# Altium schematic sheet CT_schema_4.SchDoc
size 578 x 363 mm
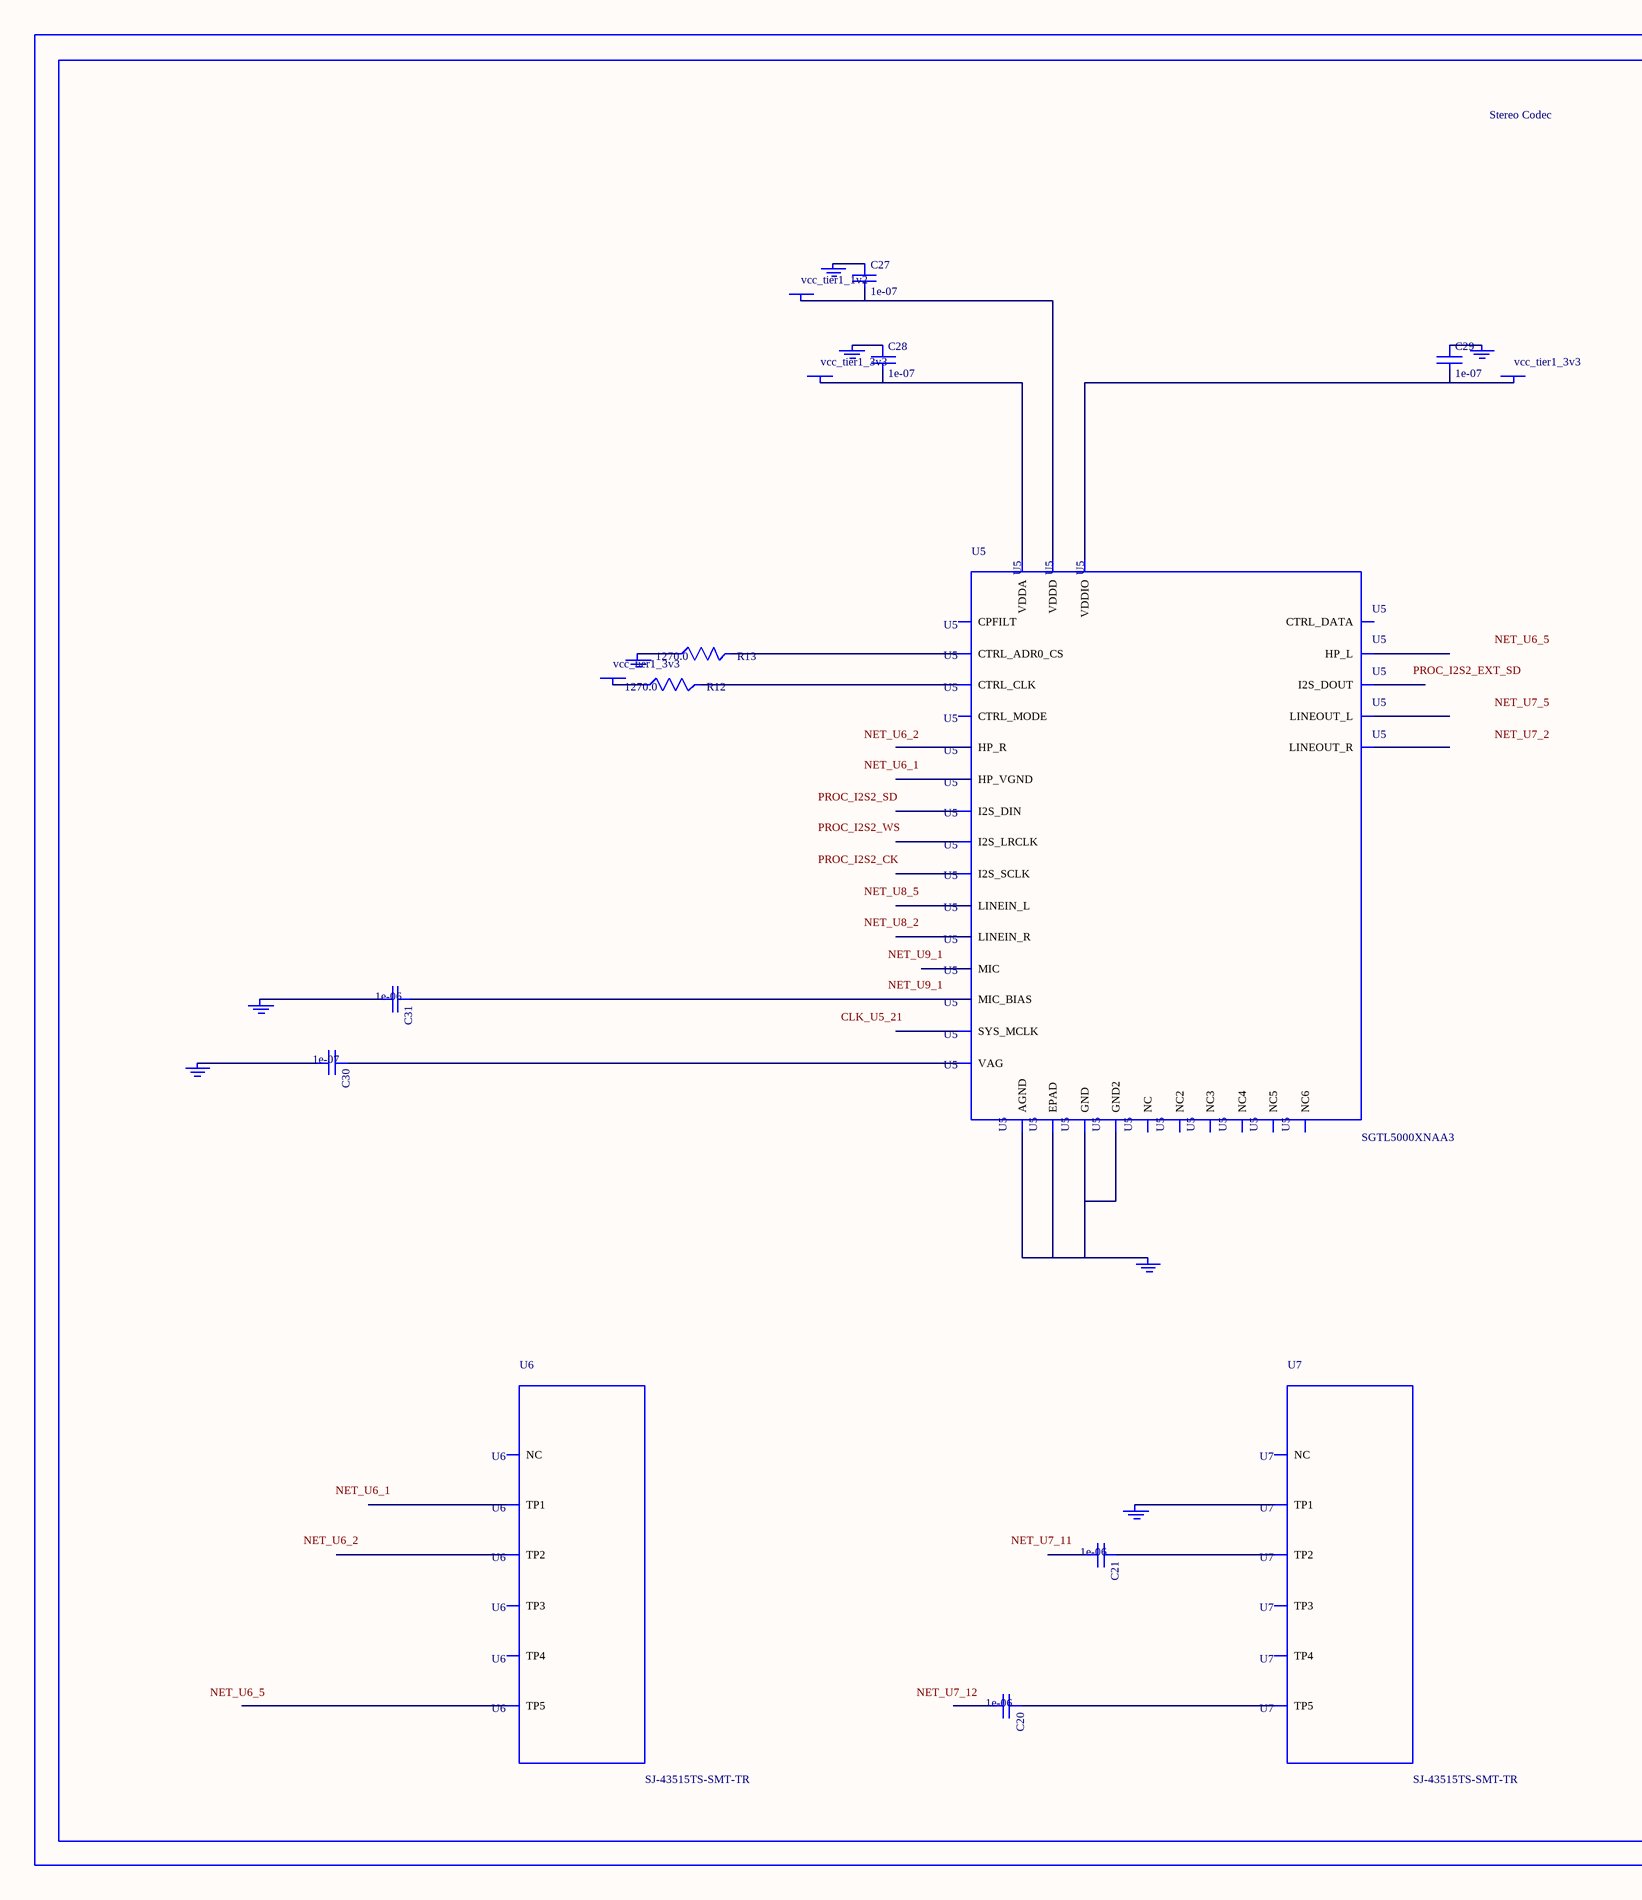
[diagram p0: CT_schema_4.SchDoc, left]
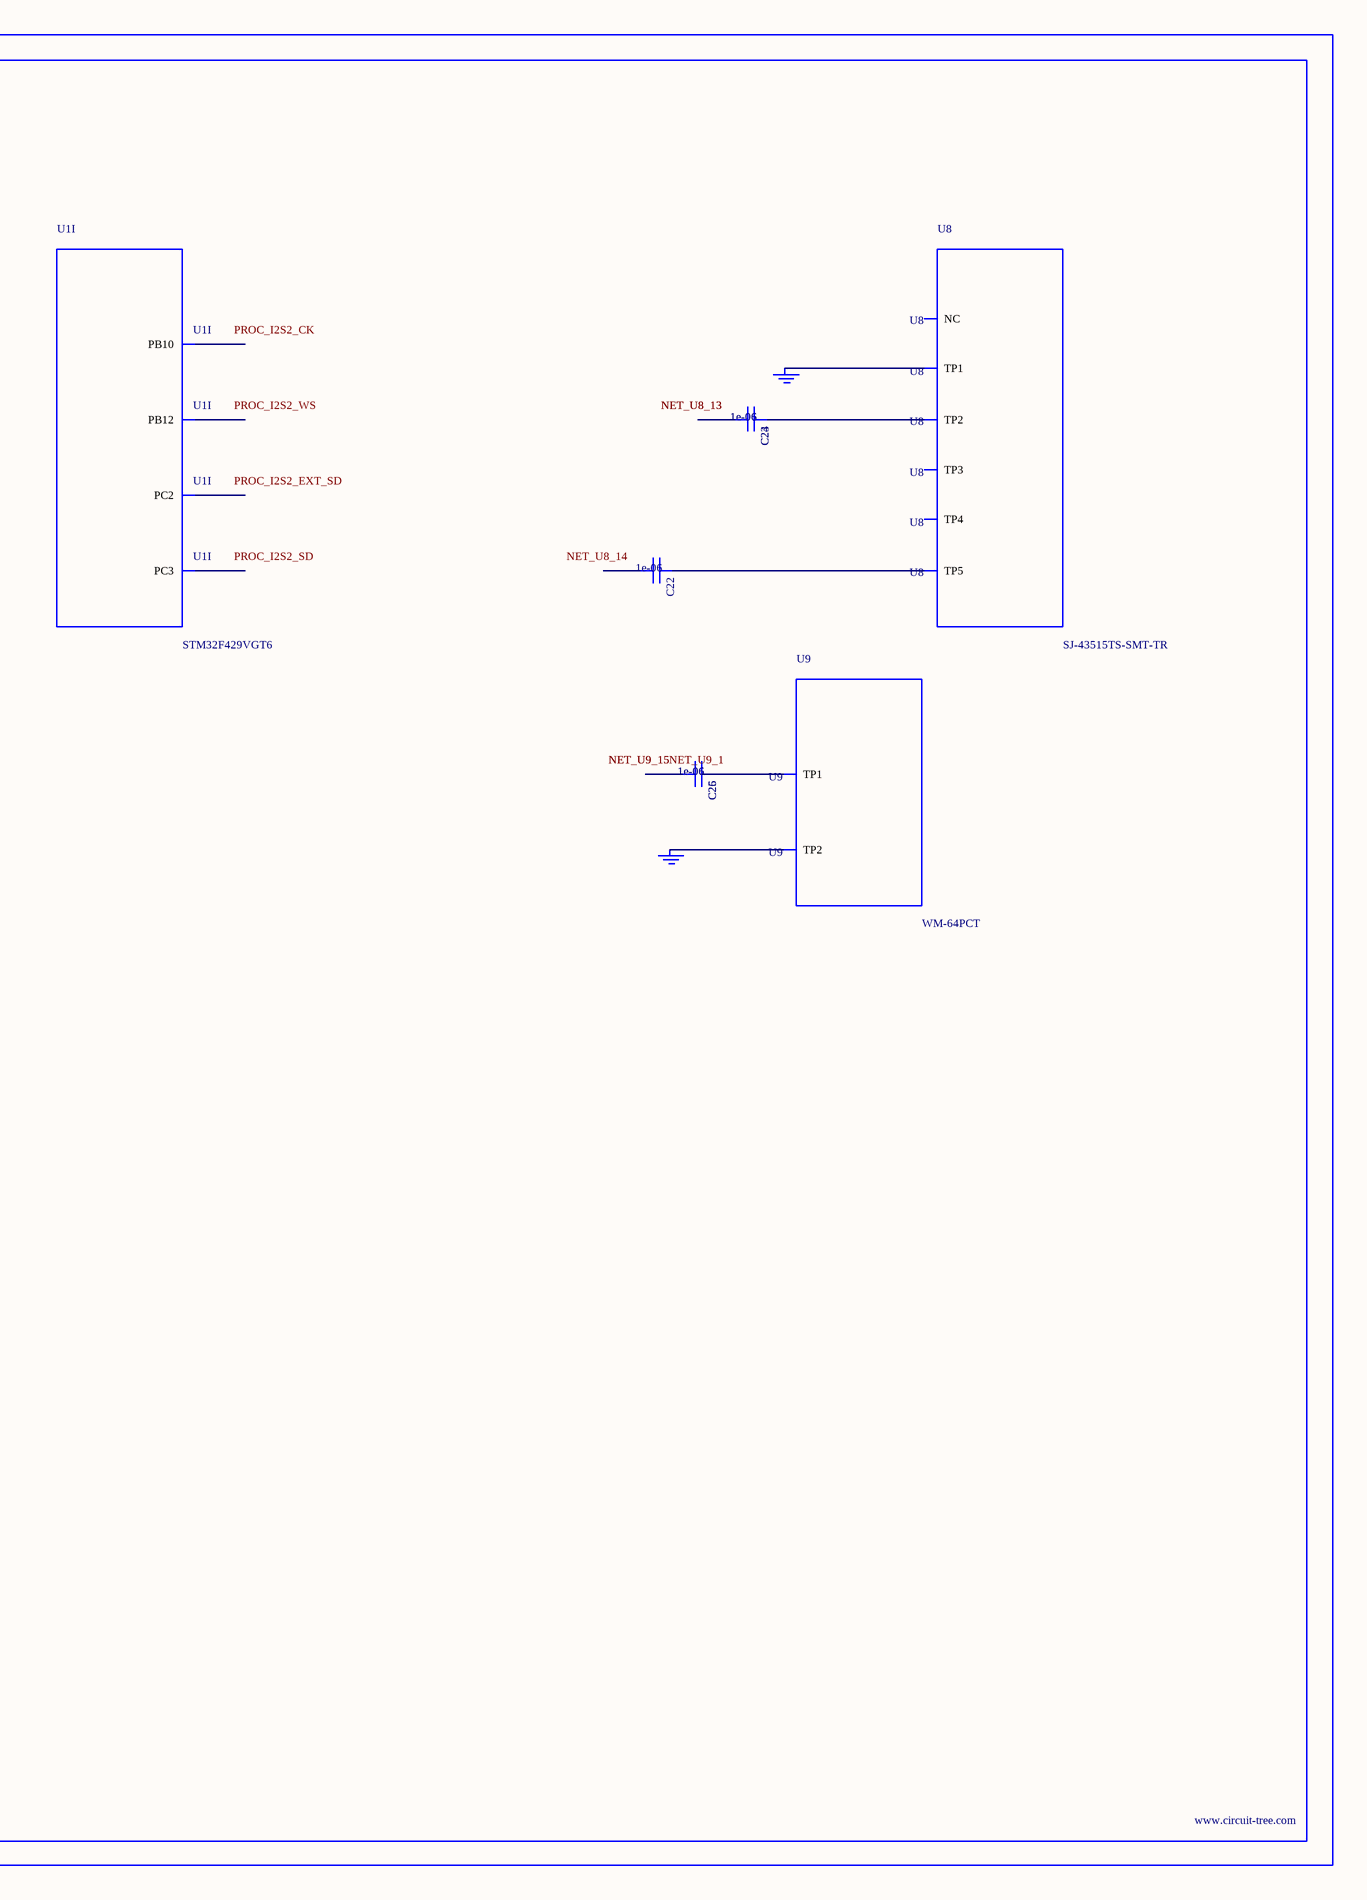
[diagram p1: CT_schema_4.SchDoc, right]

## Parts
BORDER3  (no value)
C20  1e-06  [C0603]
C21  1e-06  [C0603]
C22  1e-06  [C0603]
C23  1e-06  [C0603]
C24  1e-06  [C0603]
C25  1e-06  [C0603]
C26  1e-06  [C0603]
C27  1e-07  [C0402]
C28  1e-07  [C0402]
C29  1e-07  [C0402]
C30  1e-07  [C0402]
C31  1e-06  [C0603]
GND_INSTANCE_3_0  (no value)
GND_INSTANCE_3_1  (no value)
GND_INSTANCE_3_2  (no value)
GND_INSTANCE_3_3  (no value)
GND_INSTANCE_3_4  (no value)
GND_INSTANCE_3_5  (no value)
GND_INSTANCE_3_6  (no value)
GND_INSTANCE_3_7  (no value)
GND_INSTANCE_3_8  (no value)
GND_INSTANCE_3_9  (no value)
GND_INSTANCE_3_10  (no value)
POWER_INSTANCE_3_0  vcc_tier1_3v3
POWER_INSTANCE_3_1  vcc_tier1_3v3
POWER_INSTANCE_3_2  vcc_tier1_3v3
POWER_INSTANCE_3_3  vcc_tier1_1v2
R12  1270.0  [R0603]
R13  1270.0  [R0603]
U1  STM32F429VGT6  [LQFP100]  (part I of 10)
U5  SGTL5000XNAA3  [QFN-32]
U6  SJ-43515TS-SMT-TR  [SJ-43515TS-SMT-TR]
U7  SJ-43515TS-SMT-TR  [SJ-43515TS-SMT-TR]
U8  SJ-43515TS-SMT-TR  [SJ-43515TS-SMT-TR]
U9  WM-64PCT  [WM-64PC]

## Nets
NetC20_1: C20.1 U7.5(TP5)
NetC21_1: C21.1 U7.2(TP2)
NetC22_1: C22.1 U8.5(TP5)
NetC23_1: C23.1 C24.1 U8.2(TP2)
NetC23_2: C23.2 C24.2
NetC25_1: C25.1 C26.1 U9.1(TP1)
NetC25_2: C25.2 C26.2
NetC27_1: C27.1 GND_INSTANCE_3_5.0(GND)
NetC27_2: C27.2 POWER_INSTANCE_3_3.0(PWR) U5.30(VDDD)
NetC28_1: C28.1 GND_INSTANCE_3_1.0(GND)
NetC28_2: C28.2 POWER_INSTANCE_3_0.0(PWR) U5.5(VDDA)
NetC29_1: C29.1 GND_INSTANCE_3_4.0(GND)
NetC29_2: C29.2 POWER_INSTANCE_3_1.0(PWR) U5.20(VDDIO)
NetC30_1: C30.1 U5.10(VAG)
NetC30_2: C30.2 GND_INSTANCE_3_2.0(GND)
NetC31_1: C31.1 U5.16(MIC_BIAS)
NetC31_2: C31.2 GND_INSTANCE_3_3.0(GND)
NetGND_INSTANCE_3_0_0: GND_INSTANCE_3_0.0(GND) U5.1(GND) U5.3(GND2) U5.7(AGND) U5.EXP(EPAD)
NetGND_INSTANCE_3_6_0: GND_INSTANCE_3_6.0(GND) R13.1
NetGND_INSTANCE_3_7_0: GND_INSTANCE_3_7.0(GND) U7.1(TP1)
NetGND_INSTANCE_3_8_0: GND_INSTANCE_3_8.0(GND) GND_INSTANCE_3_9.0(GND) U8.1(TP1)
NetGND_INSTANCE_3_10_0: GND_INSTANCE_3_10.0(GND) U9.2(TP2)
NetPOWER_INSTANCE_3_2_0: POWER_INSTANCE_3_2.0(PWR) R12.1
NetR12_2: R12.2 U5.29(CTRL_CLK)
NetR13_2: R13.2 U5.31(CTRL_ADR0_CS)

Not connected (* = marked no-connect by the designer): C20 2; C21 2; C22 2; U1 17(PC2) 18(PC3) 47(PB10) 51(PB12); U5 2(HP_R) 4(HP_VGND) 6(HP_L) 8(NC) 9(NC2) 11(LINEOUT_R) 12(LINEOUT_L) 13(LINEIN_R) 14(LINEIN_L) 15(MIC) 17(NC3) 18(CPFILT) 19(NC4) 21(SYS_MCLK) 22(NC5) 23(I2S_LRCLK) 24(I2S_SCLK) 25(I2S_DOUT) 26(I2S_DIN) 27(CTRL_DATA) 28(NC6) 32(CTRL_MODE); U6 1(TP1) 2(TP2) 3(TP3) 4(TP4) 5(TP5) 6(NC); U7 3(TP3) 4(TP4) 6(NC); U8 3(TP3) 4(TP4) 6(NC)

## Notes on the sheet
- Labels drawn without touching a wire or pin: CLK_U5_21, NET_U6_1, NET_U6_2, NET_U6_5, NET_U7_2, NET_U7_5, NET_U7_11, NET_U7_12, NET_U8_2, NET_U8_5, NET_U8_14, NET_U9_1, PROC_I2S2_CK, PROC_I2S2_EXT_SD, PROC_I2S2_SD, PROC_I2S2_WS

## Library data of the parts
BORDER3 = BORDER_PAGE3
C20-C26 C31 = C0603C105K3RACTU
C27-C30 = C0402C104K3RACTU
GND_INSTANCE_3_0-GND_INSTANCE_3_10 = GND
POWER_INSTANCE_3_0-POWER_INSTANCE_3_3 = PWR
R12 R13 = RC0603FR-071K27L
